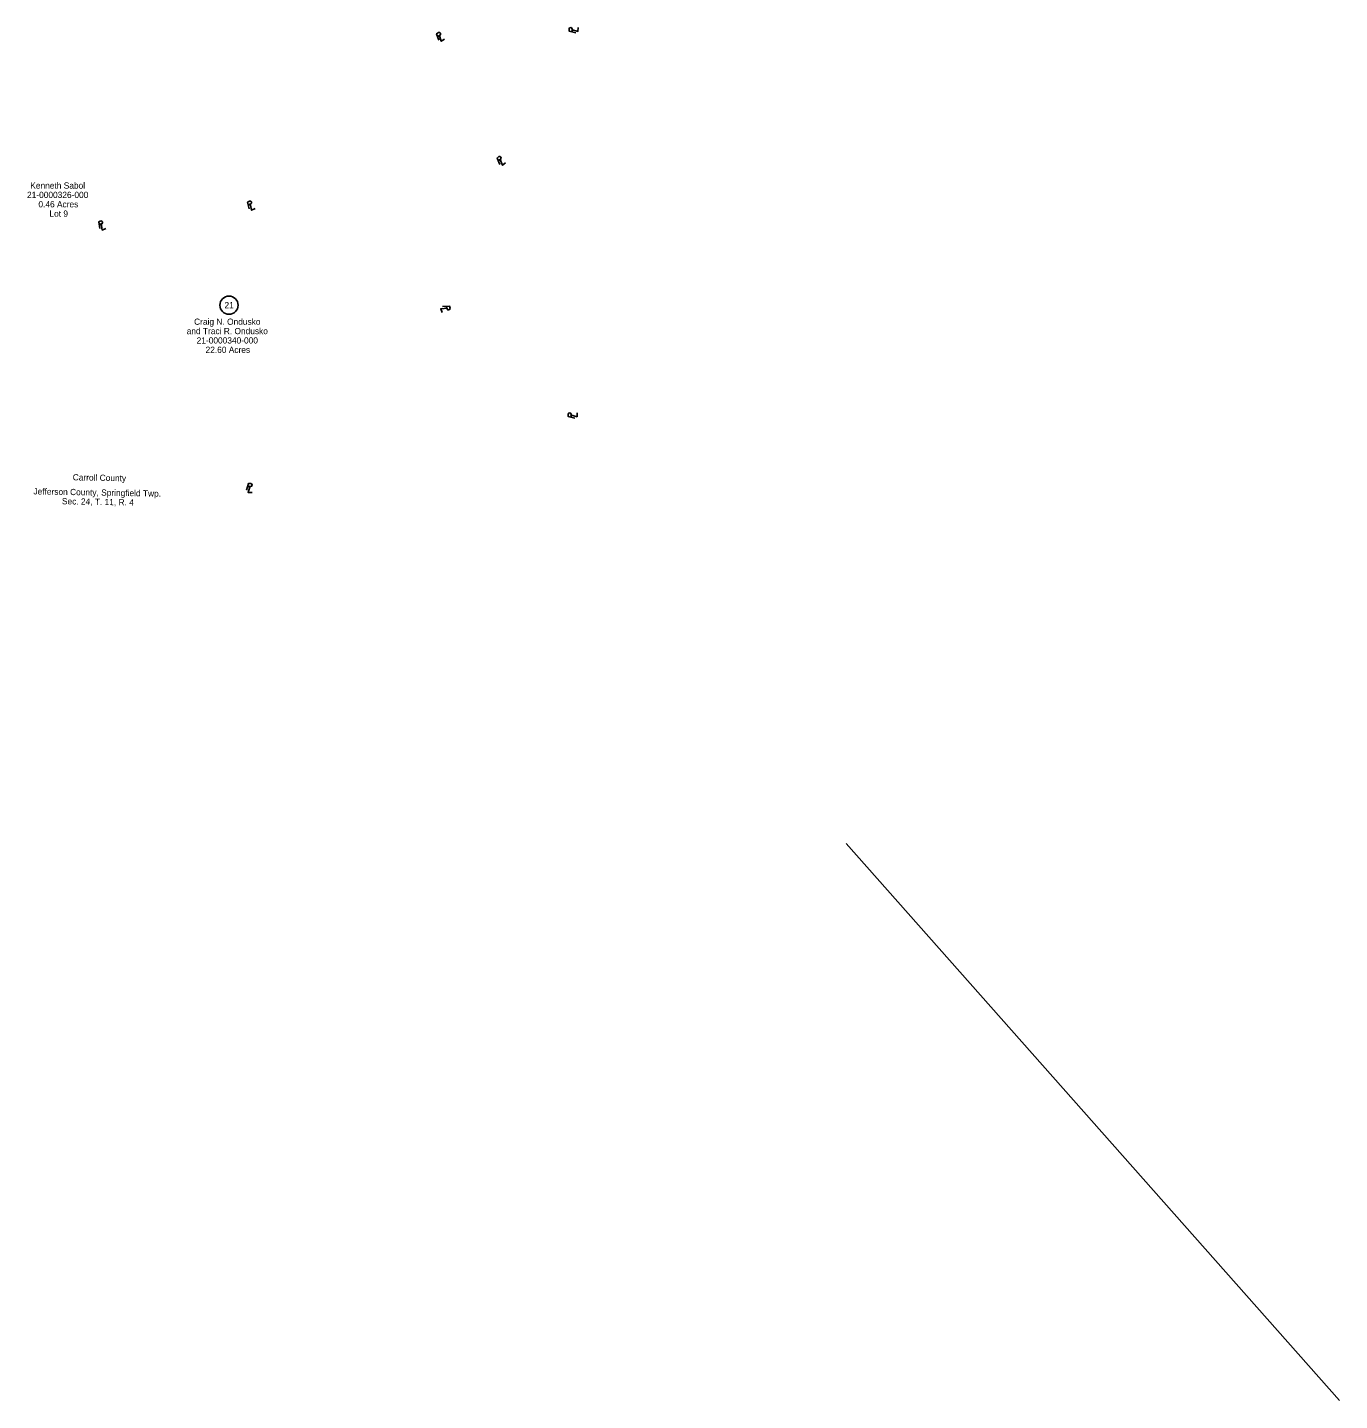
# Model space of a CAD drawing. Extents: x 250163 to 255971, y 441830 to 446572.
# Drawn here: x 253030 to 255971, y 441830 to 444909 of the extents above; entities that cross this region are included whole.
import ezdxf

# ---------------------------------------------------------------- set-up
doc = ezdxf.new("R2010")
doc.units = 0
for name, color, linetype in [('_CIVIL_CONSTRUCTION', 7, 'Continuous'), ('SH_Text', 7, 'Continuous'), ('SV_X_Text', 7, 'Continuous')]:
    doc.layers.add(name, color=color, linetype=linetype)

msp = doc.modelspace()

# ---------------------------------------------------------------- linework, layer by layer
at = {"layer": '_CIVIL_CONSTRUCTION'}
for p, q in [((254250.8, 444898.6), (254250.9, 444905.1)), ((253949.2, 444887.8), (253954.6, 444891.4)), ((253954.2, 444887.4), (253954.2, 444887.4)), ((254254, 444902.6), (254254, 444902.6)), ((254085.4, 444609.3), (254090.5, 444613.3)), ((254090.5, 444609.3), (254090.5, 444609.3)), ((253524.8, 444509.9), (253530.5, 444513)), ((253529.8, 444509.1), (253529.8, 444509.1)), ((253190.5, 444465.8), (253196.5, 444468.5)), ((253195.5, 444464.6), (253195.5, 444464.6)), ((253966.7, 444278.8), (253966.7, 444278.8)), ((253968.4, 444283.6), (253970.4, 444277.5)), ((254248.7, 444034.6), (254248.7, 444041.1)), ((254251.8, 444038.6), (254251.8, 444038.6)), ((253523.2, 443879.2), (253529.7, 443879.1)), ((253527.2, 443876), (253527.2, 443876))]:
    msp.add_line(p, q, dxfattribs=at)
for points in [[(254258.8, 444896.5), (254244, 444900.4), (254244, 444905.6)], [(254249.2, 444904), (254263.9, 444900), (254264, 444908.7)], [(253951.8, 444880), (253946.9, 444894.6), (253951.3, 444897.4)], [(253952.7, 444892.2), (253957.5, 444877.6), (253964.8, 444882.4)], [(254088.7, 444601.7), (254082.6, 444615.8), (254086.7, 444619)], [(254088.6, 444613.9), (254094.7, 444599.8), (254101.5, 444605.3)], [(253526.7, 444501.9), (253523.2, 444516.8), (253527.7, 444519.3)], [(253528.7, 444513.9), (253532.2, 444499), (253539.9, 444503.1)], [(253191.9, 444457.7), (253189.4, 444472.8), (253194.1, 444474.9)], [(253194.7, 444469.6), (253197.2, 444454.4), (253205.2, 444458)], [(253971.7, 444279.1), (253956.4, 444278.1), (253959.2, 444269.8)], [(253960.2, 444283.1), (253975.5, 444284.1), (253977.1, 444279.2)], [(254256.6, 444032.5), (254241.8, 444036.4), (254241.8, 444041.6)], [(254247, 444040), (254261.8, 444036), (254261.8, 444044.7)], [(253521, 443871.3), (253525.2, 443886.1), (253530.3, 443886)], [(253528.6, 443880.8), (253524.4, 443866.1), (253533.1, 443866)]]:
    msp.add_lwpolyline(points, dxfattribs=at)
for centre, start, end in [((254247.4, 444905.1), 0.3258, 171.1829), ((253952.7, 444894.2), 303.5552, 114.4123), ((254088.4, 444616), 308.7952, 119.6523), ((253528.9, 444516), 298.5672, 109.4243), ((253195, 444471.6), 294.7402, 105.5973), ((253973.7, 444278.6), 199.048, 9.9051), ((254245.2, 444041.1), 0.3258, 171.1829), ((253529.8, 443882.6), 269.4408, 80.2979)]:
    msp.add_arc(centre, 3.45, start, end, dxfattribs=at)
at = {"layer": 'SH_Text'}
msp.add_line((254865.3, 443079.2), (255971.3, 441830), dxfattribs=at)
at = {"layer": 'SV_X_Text'}
msp.add_circle((253481.5, 444286), 20.3, dxfattribs=at)

# ---------------------------------------------------------------- texts
for s, p in [('21-0000326-000', (253028.7, 444526.3)), ('Kenneth Sabol', (253036, 444547.3)), ('0.46 Acres', (253054.2, 444505.3)), ('Lot 9', (253078.9, 444484.3)), ('21', (253471.3, 444279)), ('Craig N. Ondusko', (253403.3, 444242)), ('and Traci R. Ondusko', (253386.6, 444221)), ('21-0000340-000', (253409, 444200)), ('22.60 Acres', (253429, 444179))]:
    msp.add_text(s, height=14, dxfattribs=at).set_placement(p)
for s, p in [('Carroll County', (253131.1, 443893.2)), ('Jefferson County, Springfield Twp.', (253042.9, 443861.7)), ('Sec. 24, T. 11, R. 4', (253106.8, 443839.6))]:
    msp.add_text(s, height=14, rotation=358.9698, dxfattribs=at).set_placement(p)

doc.saveas('drawing.dxf')
